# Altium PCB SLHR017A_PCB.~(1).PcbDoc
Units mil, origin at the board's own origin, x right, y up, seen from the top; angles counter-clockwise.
Board outline 3125 x 2100 mil, 2 copper layers (Top Layer, Bottom Layer), stack 61.2 mil thick; 71 components, 26 nets, 111 pads, 51 vias.
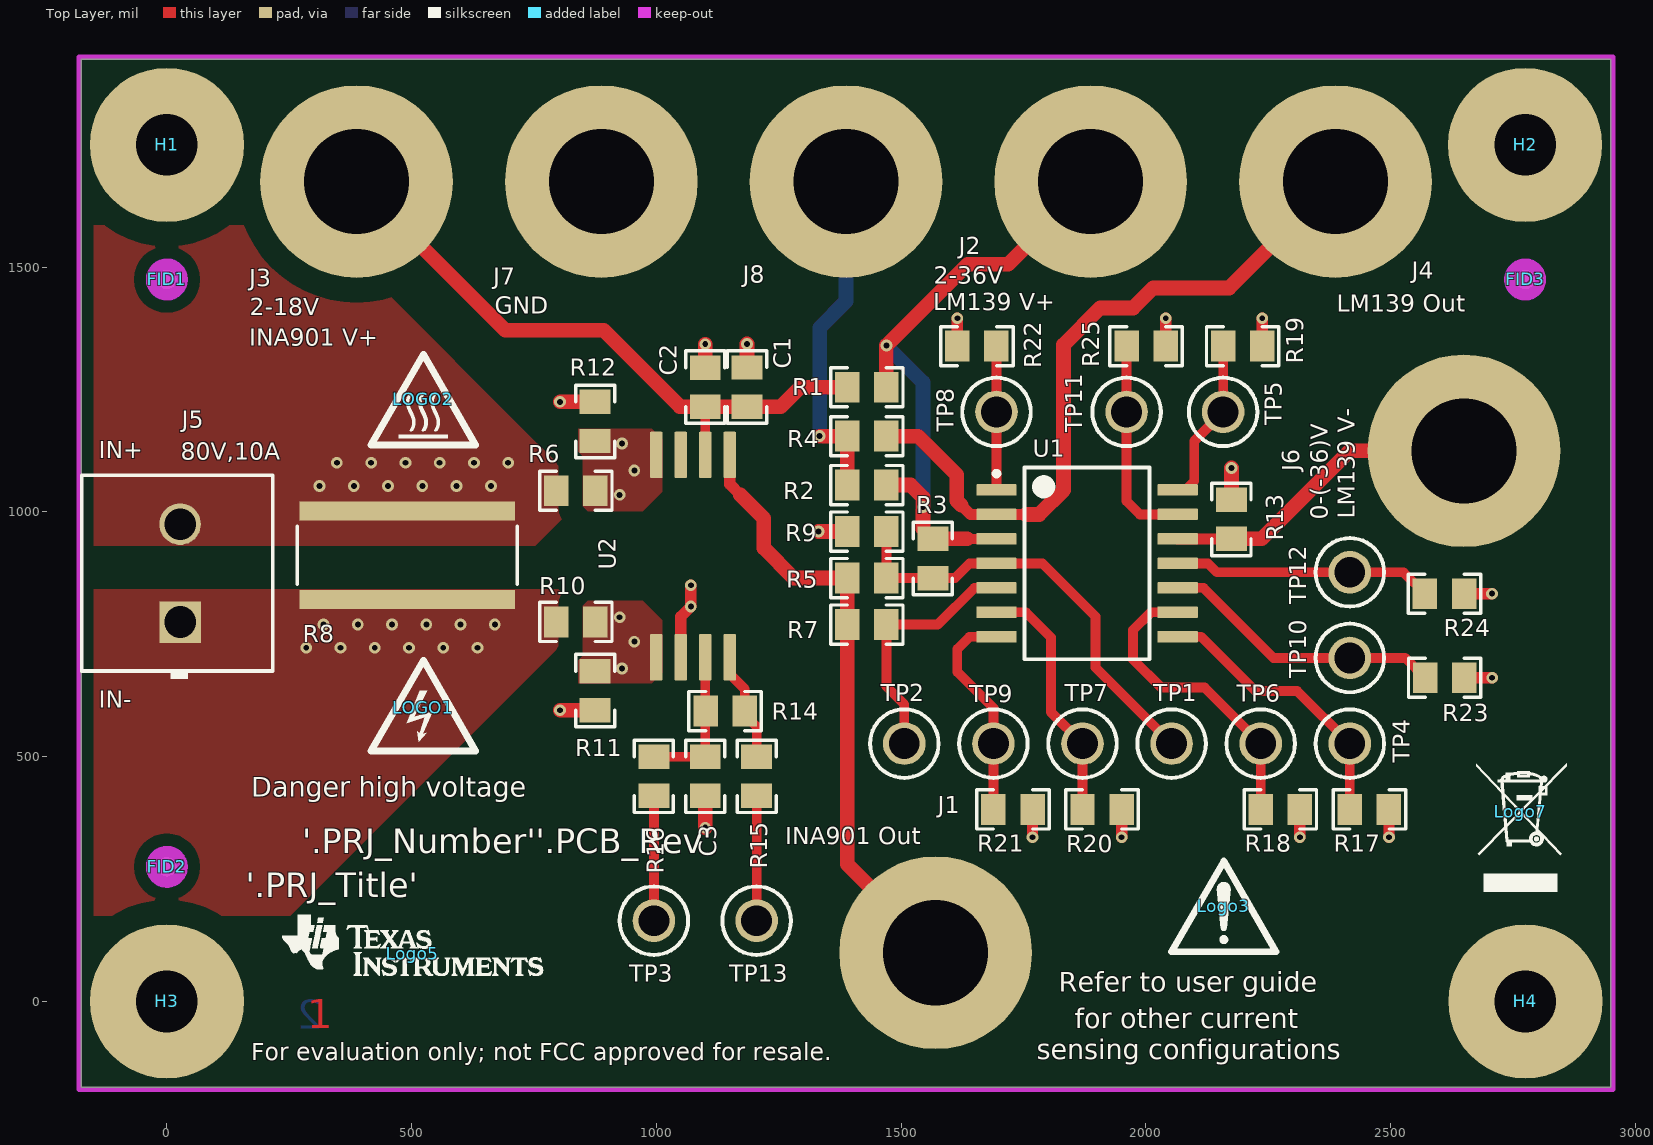
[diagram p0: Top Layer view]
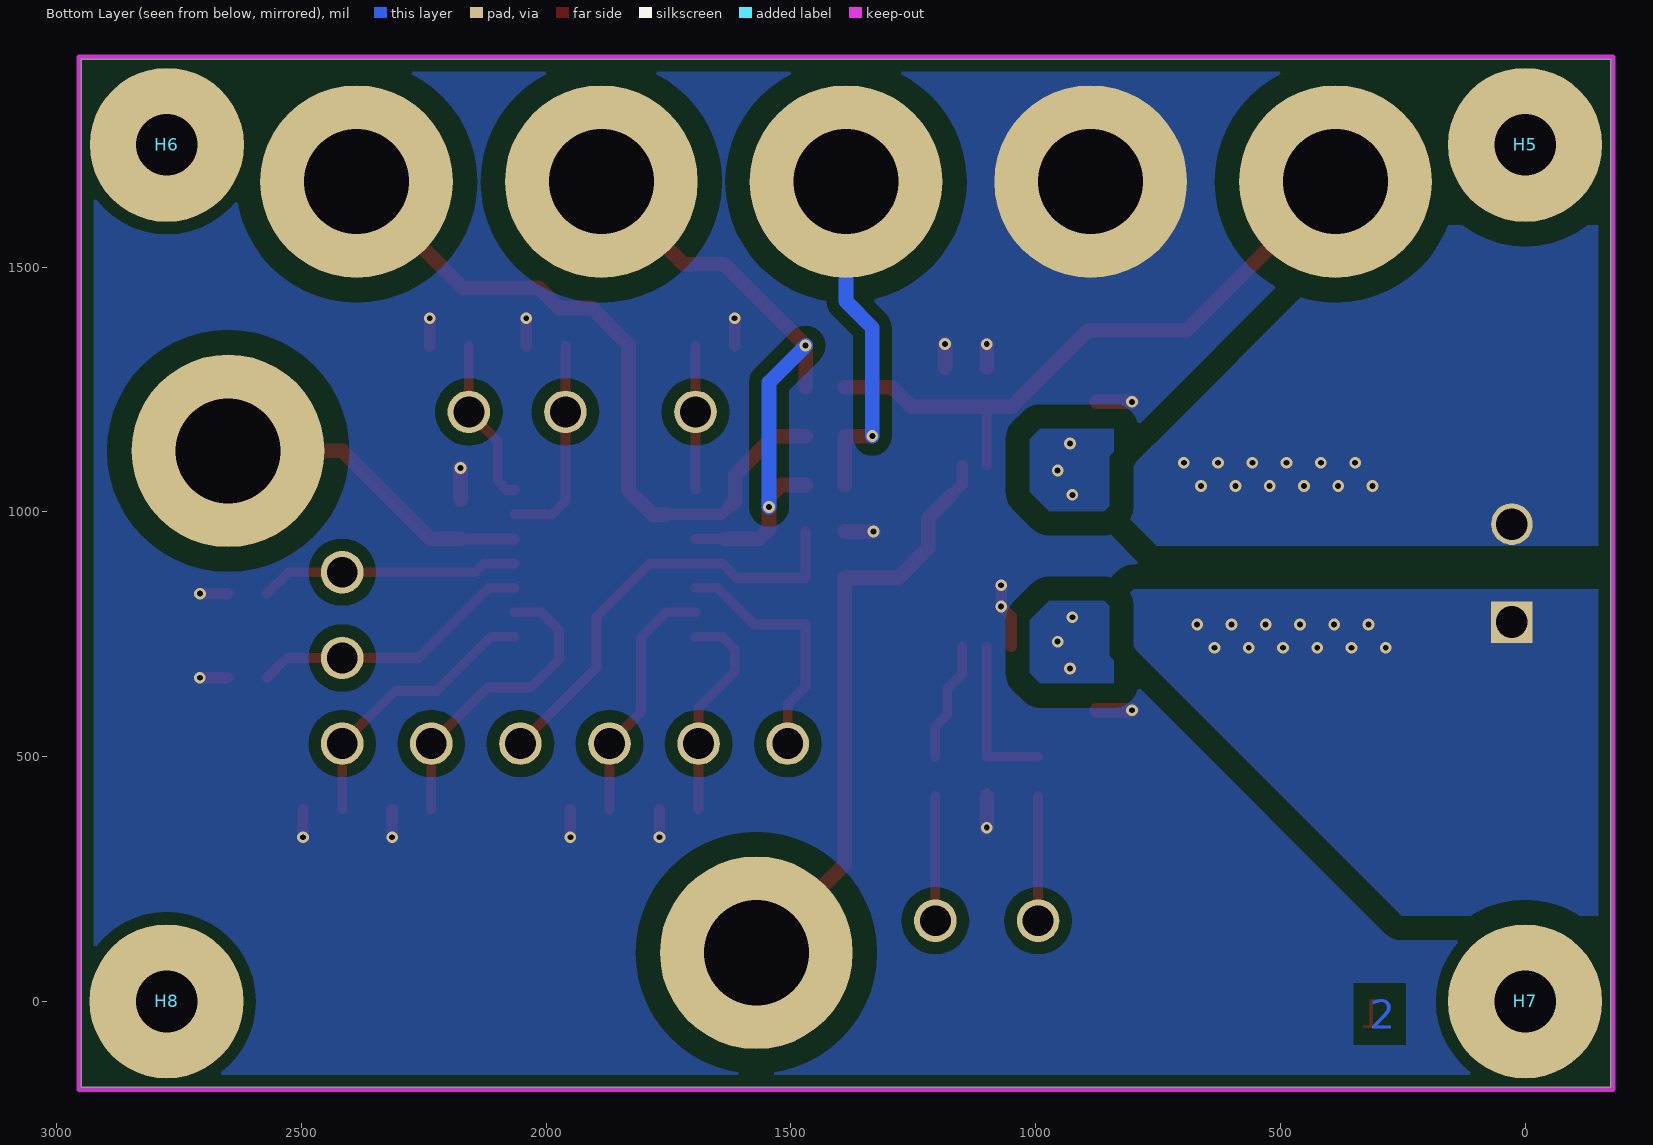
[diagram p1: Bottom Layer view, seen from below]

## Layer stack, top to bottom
Top Solder: solder mask 0.4, Solder Resist, Dk 3.5
Top Layer: signal copper 2.1
Dielectric1: core 57, FR-4 High Tg, Dk 4.8
Bottom Layer: signal copper 2.1
Bottom Solder: solder mask 0.4, Solder Resist, Dk 3.5

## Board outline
-175,-175 2950,-175 2950,1925 -175,1925
cut-out: -1791.23,-2214.56 -1781.23,-2214.56 -1781.23,-2204.56 -1791.23,-2204.56

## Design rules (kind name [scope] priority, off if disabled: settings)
AcuteAngle [All] p1: minimum=4.50000000000000E+0001 checktracksonly=FALSE
AssemblyTestPointUsage [All] p1: valid=2
Clearance Clearance_HV [InNetClass('HV_Net')] p1: gap=25 ignorepadtopadclearanceinfootprint=TRUE except(50: THPad-Poly Poly-Poly)
Clearance Clearance_Keepouts [((IsTrack Or IsArc) And Not InPoly) And IsFree and IsKeepOut vs ((IsTrack Or IsArc) And Not InPoly) And IsFree and IsKeepOut] p2: gap=0 ignorepadtopadclearanceinfootprint=FALSE
Clearance Clearance_Fiducial [InComponentClass('FiducialMark')] p3: gap=0 ignorepadtopadclearanceinfootprint=FALSE
Clearance Clearance_BoardEdge_MountingHoles [OnCopper and InComponentClass('Mounting Holes') vs IsKeepOut] p4: gap=40 ignorepadtopadclearanceinfootprint=FALSE except(15: Track-THPad)
Clearance Clearance_BoardEdge_Poly [OnCopper and InPoly vs IsKeepOut] p5: gap=25 ignorepadtopadclearanceinfootprint=FALSE
Clearance Clearance_Jack_Poly [InPolygon vs InPadClass('Jack')] p6: gap=25 ignorepadtopadclearanceinfootprint=FALSE except(50: Arc-Poly Track-Poly SMDPad-Poly THPad-Poly Via-Poly Fill-Poly Poly-Poly)
Clearance Clearance_Poly [InPolygon] p7: gap=25 ignorepadtopadclearanceinfootprint=FALSE
Clearance [All] p8: gap=15 ignorepadtopadclearanceinfootprint=FALSE
ComponentClearance ComponentClearance_MountingHoles_FiducialMarks [InComponentClass('Mounting Holes') vs InComponentClass('FiducialMark')] p1: gap=50 collisioncheckmode=3 verticalgap=10 showdistances=FALSE
ComponentClearance ComponentClearance_Logo [InComponentClass('Logo')] p2: gap=50 collisioncheckmode=3 verticalgap=100000 showdistances=FALSE
ComponentClearance ComponentClearance_ScrewToNut [(HasFootprint('NY PMS 440 0025 PH')) vs (HasFootprint('Keystone_1902C'))] p3: gap=0 collisioncheckmode=3 verticalgap=0 showdistances=FALSE
ComponentClearance ComponentClearance_MountingHoles [InComponentClass('Mounting Holes')] p4: gap=30 collisioncheckmode=3 verticalgap=100000 showdistances=FALSE
ComponentClearance [All] p5: gap=20 collisioncheckmode=3 verticalgap=10 showdistances=FALSE
DiffPairsRouting [All] p1: maxlimit=100 minlimit=10 mostfreqgap=10 toplayer_minwidth=15 toplayer_maxwidth=15 toplayer_prefwidth=15 bottomlayer_minwidth=15 bottomlayer_maxwidth=15 bottomlayer_prefwidth=15 maxuncoupledlength=1000
FabricationTestPointUsage TestPointUsage [All] p1: valid=2 allowmultiple=FALSE
FabricationTestpoint Testpoint [All] p1: side=3 testpointundercomponent=TRUE minsize=40 maxsize=100 preferedsize=60 minholesize=0 maxholesize=40 preferedholesize=32 testpointgrid=1 allowsidetop=TRUE allowsidebottom=TRUE usegrid=TRUE gridtolerance=0.01
FanoutControl Fanout_LCC [IsLCC] p1: bgadir=Out bgaviamode=Centered fanoutstyle=Auto fanoutdirection=Alternating viagrid=1 // Fanout_LCC (Default Rule)
FanoutControl Fanout_BGA [IsBGA] p2: bgadir=Out bgaviamode=Centered fanoutstyle=Auto fanoutdirection=Alternating viagrid=1 // Fanout_BGA (Default Rule)
FanoutControl Fanout_Default [All] p4: bgadir=Out bgaviamode=Centered fanoutstyle=Auto fanoutdirection=Alternating viagrid=1 // Fanout_Default (Default Rule)
FanoutControl Fanout_Small [(CompPinCount < 5)] p5: bgadir=Out bgaviamode=Centered fanoutstyle=Auto fanoutdirection=OutThenIn viagrid=1 // Fanout_Small (Default Rule)
HoleSize [All] p1: absolutevalues=TRUE maxlimit=251 minlimit=8 maxpercent=80.000 minpercent=20.000
MinimumAnnularRing [All] p1: minimumring=6
MinimumSolderMaskSliver MinimumSolderMaskSliver_Logo [InComponentClass('Logo') vs InComponentClass('Logo')] p1: minsoldermaskwidth=0.7
MinimumSolderMaskSliver [All] p2: minsoldermaskwidth=4
PlaneConnect [All] p1: planeconnectstyle=Relief reliefexpansion=10 reliefentries=4 reliefconductorwidth=10 reliefairgap=10
PolygonConnect [All] p1: connectstyle=Direct reliefconductorwidth=30 reliefentries=4 polygonreliefangle="90 Angle" airgapwidth=15
RoutingVias [All] p1: holewidth=12 width=24 viastyle="Through Hole" minholewidth=12 minwidth=24 maxholewidth=12 maxwidth=24
SilkToBoardRegionClearance [Not ((IsComment or IsDesignator) And (Hide <> 'False')) and not InRegion(1000,500,4000,800)] p1:
SilkToSilkClearance SilkToSilkClearance_Pb-FreeLogo [(HasFootprint('Pb-Free_Overlay_Medium') OR HasFootprint('Pb-Free_Overlay_Small')) vs (HasFootprint('Pb-Free_Overlay_Medium') OR HasFootprint('Pb-Free_Overlay_Small'))] p1: silktosilkclearance=0
SilkToSilkClearance [All] p2: silktosilkclearance=4
SilkToSolderMaskClearance SilkToComonentPadClearance [IsPad and InAnycomponent] p1: minsilkscreentomaskgap=5 clearancetoexposedcopper=TRUE
SilkToSolderMaskClearance "Silk to Solder Mask Opening" [All] p2: minsilkscreentomaskgap=4 clearancetoexposedcopper=FALSE
SolderMaskExpansion [All] p1: expansion=0
Width [All] p1: maxlimit=100 minlimit=6 preferedwidth=10 checkconnectedcopper=TRUE
15 further rules are at their usual default settings.

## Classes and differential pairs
net class HV_Net: NetJ5_1 NetJ5_2 NetR6_2 NetR10_2
pad class "HV Jack": J1-1
pad class Jack: J1-1 J2-1 J3-1 J4-1 J6-1 J7-1 J8-1
component class "Mounting Holes": H1 H2 H3 H4
component class Logo: Logo5
component class SLHR017A_Hardware: FID1 FID2 FID3 H1 H2 H3 H4 H5 H6 H7 H8 LOGO1 LOGO2 Logo3 Logo5 Logo6 Logo7 ZZ1 ZZ2 ZZ3
component class FiducialMark: FID1 FID2 FID3
component class AssemblyNote: ZZ1 ZZ2 ZZ3
component class SLHR017A_MainSheet: C1 C2 C3 J1 J2 J3 J4 J5 J6 J7 J8 R1 R2 R3 R4 R5 R6 R7 R8 R9 R10 R11 R12 R13 R14 R15 R16 R17 R18 R19 R20 R21 R22 R23 R24 R25 TP1 TP2 TP3 TP4 TP5 TP6 TP7 TP8 TP9 TP10 TP11 TP12 TP13 U1 U2 U4

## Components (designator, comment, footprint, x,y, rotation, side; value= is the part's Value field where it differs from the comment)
C1 "C0805C104K1RACTU" 0805_HV 1185.18,1255.18 r90 top locked value=0.1uF
C2 "C0805C103F1GACTU" 0805_HV 1100,1255 r90 top locked value=0.01uF
C3 "C0805C103F1GACTU" 0805_HV 1100,460 r270 top locked value=0.01uF
FID1 "Fiducial" Fiducial10-20 0,1475 r270 top locked
FID2 "Fiducial" Fiducial10-20 0,275 r0 top locked
FID3 "Fiducial" Fiducial10-20 2775,1475 r180 top locked
H1 "NY PMS 440 0025 PH" "NY PMS 440 0025 PH" 0,1750 r0 top locked
H2 "NY PMS 440 0025 PH" "NY PMS 440 0025 PH" 2775,1750 r0 top locked
H3 "NY PMS 440 0025 PH" "NY PMS 440 0025 PH" 0,0 r0 top locked
H4 "NY PMS 440 0025 PH" "NY PMS 440 0025 PH" 2775.53,0 r0 top locked
H5 "1902C" Keystone_1902C 0,1750 r180 bottom locked
H6 "1902C" Keystone_1902C 2775,1750 r180 bottom locked
H7 "1902C" Keystone_1902C 0,0 r180 bottom locked
H8 "1902C" Keystone_1902C 2775.53,0 r180 bottom locked
J1 "575-4" Keystone_575-4 1570.77,99.44 r0 top locked
J2 "575-4" Keystone_575-4 1887.5,1675 r0 top locked
J3 "575-4" Keystone_575-4 387.5,1675 r0 top locked
J4 "575-4" Keystone_575-4 2387.5,1675 r0 top locked
J5 "039544-3002" Molex_039544-3002 27.17,875 r90 top locked
J6 "575-4" Keystone_575-4 2650,1125 r0 top locked
J7 "575-4" Keystone_575-4 887.5,1675 r0 top locked
J8 "575-4" Keystone_575-4 1387.5,1675 r0 top locked
LOGO1 "DANGER HIGH VOLTAGE" IEC_HighVoltage_Small 524,599.72 r0 top
LOGO2 "CAUTION HOT SURFACE" IEC_HotSurface_Small 524,1229.94 r0 top
Logo3 "CAUTION.  READ USER GUIDE BEFORE USE" IEC_Caution_Small 2159.38,194.38 r0 top
Logo5 "Texas Instruments" TI_Stacked_Overlay_Small 502.13,97.86 r0 top
Logo6 "FCC disclaimer" FCC_disclaimer 1947.51,-1477.18 r270 top locked
Logo7 "WEEE logo" WEEE_Minimum 2765.79,387.53 r0 top
R1 "ERJ-6GEY0R00V" 0805_HV 1430,1255 r180 top locked value=0
R2 "ERJ-6GEY0R00V" 0805_HV 1430,1055 r180 top locked value=0
R3 "ERJ-6GEYJ153V" 0805_HV 1565,905 r90 top locked value=15k
R4 "ERJ-6GEYJ302V" 0805_HV 1430,1155 r180 top locked value=3.0k
R5 "ERJ-6GEY0R00V" 0805_HV 1430,865 r0 top locked value=0
R6 "ERJ-6GEY0R00V" 0805_HV 835.36,1043.51 r0 top locked value=0
R7 "ERJ-6GEY0R00V" 0805_HV 1430,770 r0 top locked value=0
R8 "KRL11050-C-R050-F-T1" 4320 490.99,911.59 r90 top locked value=0.05
R9 "ERJ-6GEYJ153V" 0805_HV 1430,960 r0 top locked value=15k
R10 "ERJ-6GEY0R00V" 0805_HV 835.36,775.33 r0 top locked value=0
R11 "ERJ-6GEY0R00V" 0805_HV 875,635 r90 top locked value=0
R12 "ERJ-6GEY0R00V" 0805_HV 875,1185 r270 top locked value=0
R13 "ERJ-6GEY0R00V" 0805_HV 2174.96,985 r270 top locked value=0
R14 "ERJ-6GEY0R00V" 0805_HV 1140.6,593.26 r180 top locked value=0
R15 "ERJ-6GEY0R00V" 0805_HV 1204.96,460 r90 top locked value=0
R16 "ERJ-6GEY0R00V" 0805_HV 994.96,460 r90 top locked value=0
R17 "ERJ-6GEY0R00V" 0805_HV 2456.86,392.33 r180 top value=0
R18 "ERJ-6GEY0R00V" 0805_HV 2274.81,392.33 r180 top value=0
R19 "ERJ-6GEY0R00V" 0805_HV 2198.08,1338.86 r180 top value=0
R20 "ERJ-6GEY0R00V" 0805_HV 1910.71,392.33 r180 top value=0
R21 "ERJ-6GEY0R00V" 0805_HV 1728.67,392.33 r180 top value=0
R22 "ERJ-6GEY0R00V" 0805_HV 1654.96,1338.86 r0 top value=0
R23 "ERJ-6GEY0R00V" 0805_HV 2610.76,661.33 r180 top value=0
R24 "ERJ-6GEY0R00V" 0805_HV 2610.39,833.07 r180 top value=0
R25 "ERJ-6GEY0R00V" 0805_HV 2000.77,1338.86 r180 top value=0
TP1 "5010" Keystone5010 2052.76,526.75 r90 top locked
TP2 "5010" Keystone5010 1506.62,526.75 r90 top locked
TP3 "5010" Keystone5010 994.96,164.96 r90 top locked
TP4 "5010" Keystone5010 2416.86,526.75 r90 top locked
TP5 "5010" Keystone5010 2158.08,1204.44 r90 top locked
TP6 "5010" Keystone5010 2234.81,526.75 r90 top locked
TP7 "5010" Keystone5010 1870.71,526.75 r90 top locked
TP8 "5010" Keystone5010 1694.96,1204.44 r90 top locked
TP9 "5010" Keystone5010 1688.67,526.75 r90 top locked
TP10 "5010" Keystone5010 2416.86,701.75 r90 top locked
TP11 "5010" Keystone5010 1960.77,1204.44 r90 top locked
TP12 "5010" Keystone5010 2416.86,876.75 r90 top locked
TP13 "5010" Keystone5010 1204.96,164.96 r90 top locked
U1 "LM139AWGRLQMLV" NAC0014A_N 1880,895 r0 top locked
U2 "INA901HKX/EM" HKX0008A_Custom_B 1075,910 r90 top locked
ZZ1 "These assemblies are ESD sensitive, ESD precautions shall be observed." AssemblyNote 4427.97,1278.79 r0 top
ZZ2 "These assemblies must be clean and free from flux and all contaminants. Use of no clean flux is not acceptable." AssemblyNote 4427.97,1190.24 r0 top
ZZ3 "These assemblies must comply with workmanship standards IPC-A-610 Class 2, unless otherwise specified." AssemblyNote 4427.97,1101.68 r0 top

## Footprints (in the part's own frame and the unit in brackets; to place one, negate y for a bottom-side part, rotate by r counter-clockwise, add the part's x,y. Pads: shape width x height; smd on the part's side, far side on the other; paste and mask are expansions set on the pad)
0805_HV [mil] "0805 with 30mil clearance between pads"
  rect 50x63 smd: 1(-40,0) 2(40,0)
  silkscreen extent -74,-40 74,40, body extent -43,-29 43,29, height 57
4320 [mm] "SUSUMU"
  rect 1x11.2 smd: 1(-2.3,0) 2(2.3,0)
  silkscreen extent -1.5,-5.7 1.5,5.7, body extent -2.6,-5.6 2.6,5.6, height 0.7
AssemblyNote [mil] "Assembly Note"
FCC_disclaimer [mil]
Fiducial10-20 [mm]
  round 1 smd mask+0.5: 1(0,0)
  Top Layer keep-out circle w1.178: c0,0 r0.5
HKX0008A_Custom_B [mm] "CFP, 8-Leads, Body 6.73x6.74mm (max), Pitch 1.27mm, IPC Medium Density"
  rrect15% 2.4x0.65 smd: 1(-5.25,1.905) 2(-5.25,0.635) 3(-5.25,-0.635) 4(-5.25,-1.905) 5(5.25,-1.905) 6(5.25,-0.635) 7(5.25,0.635) 8(5.25,1.905)
  body extent -3.25,-3.24 3.25,3.24, height 2.51
IEC_Caution_Small [mil]
  silkscreen extent -107,-93 107,92
IEC_HighVoltage_Small [mil]
  silkscreen extent -107,-88 107,97
IEC_HotSurface_Small [mil]
  silkscreen extent -107,-93 107,92
Keystone5010 [mil] "Keystone Multipurpose loops"
  round 87 hole 63: 1(0,0)
  silkscreen extent -70,-70 70,70, body extent -63,-63 63,62, height 319
Keystone_575-4 [mm] "Banana Jack"
  round 10 hole 5.45: 1(0,0)
  body extent -3.95,-3.95 3.92,3.93, height 2.36
Keystone_1902C [mil] "Hex Standoff, 4-40 threaded, nylon"
  round 1 on Mech4: 0(0,0)
  body extent -145,-126 146,126, height 501
Molex_039544-3002 [mm] "Terminal Block, 5.08mm, 2x1, TH"
  rect 2.15x2.15 hole 1.65: 1(-2.54,0)
  round 2.15 hole 1.65: 2(2.54,0)
  silkscreen extent -5.5,-4.8 5.08,5.11, body extent -5.08,-4.8 5.08,5.11, height 14.48
NAC0014A_N [mm] "CFP-14"
  rrect17% 2.1x0.6 smd: 1(-4.7,3.81) 2(-4.7,2.54) 3(-4.7,1.27) 4(-4.7,0) 5(-4.7,-1.27) 6(-4.7,-2.54) 7(-4.7,-3.81) 8(4.7,-3.81) 9(4.7,-2.54) 10(4.7,-1.27) 11(4.7,0) 12(4.7,1.27) 13(4.7,2.54) 14(4.7,3.81)
  silkscreen extent -4.82,-4.97 3.25,4.97, body extent -5.21,-4.95 5.21,4.95, height 1.99
"NY PMS 440 0025 PH" [mm] "4-40 nylon screw and mounting hole"
  round 8 hole 3.2: 1(0,0)
  body extent -3.3,-3.3 3.3,3.3, height 2.69
TI_Stacked_Overlay_Small [mil]
  silkscreen extent -267,-46 267,80
WEEE_Minimum [mil] "WEEElie bin"
  silkscreen extent -91,-164 94,99

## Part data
C1: library part CMP-0007722-2, "CAP, CERM, 0.1 uF, 100 V, +/- 10%, X7R, 0805", Cap_Case=0805, Manufacturer=Kemet, Supplier Part Number 1=399-3486-1-ND, TempCo=X7R, Tolerance_%=10%, Value1="0.064 ohm", Value2=100V, ValueDisplayed=0.1uF
C2 C3: library part CMP-0007716-2, "CAP, CERM, 0.01 uF, 100 V, +/- 1%, C0G/NP0, 0805", Cap_Case=0805, Manufacturer=Kemet, Supplier Part Number 1=399-11160-1-ND, TempCo=C0G/NP0, Tolerance_%=1%, Value1=Unknown, Value2=100V, ValueDisplayed=0.01uF
FID1 FID2 FID3: library part CMP-0077181-1, "Fiducial mark.  There is nothing to buy or mount.", Manufacturer=N/A
H1 H2 H3 H4: library part CMP-0003617-1, "Machine Screw, Round, #4-40 x 1/4, Nylon, Philips panhead", Manufacturer="B&F Fastener Supply", Supplier Part Number 1=H542-ND
H5 H6 H7 H8: library part CMP-0003610-1, "Standoff, Hex, 0.5\"L #4-40 Nylon", Manufacturer=Keystone, Supplier Part Number 1=36-1902C-ND
J1 J2 J3 J4 J6 J7 J8: library part CMP-0055165-2, "Standard Banana Jack, Uninsulated, 5.5mm", Manufacturer=Keystone, Supplier Part Number 1=36-575-4-ND
J5: library part CMP-0055345-1, "Terminal Block, 5.08mm, 2x1, TH", Color=Black, Current_A=15A, Manufacturer=Molex, Supplier Part Number 1=WM7853-ND, Voltage_V=300V
LOGO1: library part CMP-0074835-1, "IEC 61010-1 High Voltage Warning"
LOGO2: library part CMP-0074837-1, "IEC 61010-1 Hot Surface Warning"
Logo3: library part CMP-0074836-1, "IEC 61010-1 Caution Warning"
Logo5: library part CMP-0074838-1, "Texas Instrument Corporate Signature"
Logo6: library part CMP-0074847-1, "FCC_disclaimer"
Logo7: library part CMP-0074769-1
R1 R2 R5 R6 R7 R10 R11 R12 R13 R14 R15 R16 R17 R18 R19 R20 R21 R22 R23 R24 R25: library part CMP-0020616-3, "RES, 0, 5%, 0.125 W, AEC-Q200 Grade 0, 0805", Manufacturer=Panasonic, Power_W=125mW, Supplier Part Number 1=P0.0ACT-ND, TempCo="600 ppm/C", Tolerance_%=5%, Value2=0.125W, Value_Code=0000, ValueDisplayed=0
R3 R9: library part CMP-0020646-3, "RES, 15 k, 5%, 0.125 W, AEC-Q200 Grade 0, 0805", Manufacturer=Panasonic, Power_W=125mW, Supplier Part Number 1=P15KACT-ND, TempCo="200 ppm/C", Tolerance_%=5%, Value2=0.125W, Value_Code=15k0, ValueDisplayed=15k
R4: library part CMP-0020698-3, "RES, 3.0 k, 5%, 0.125 W, AEC-Q200 Grade 0, 0805", Manufacturer=Panasonic, Power_W=125mW, Supplier Part Number 1=P3.0KACT-ND, TempCo="200 ppm/C", Tolerance_%=5%, Value2=0.125W, Value_Code=3k00, ValueDisplayed=3.0k
R8: library part CMP-0015099-2, "RES, 0.05, 1%, 6 W, 4320_WIDE", Manufacturer="Susumu Co Ltd", Power_W=6W, Supplier Part Number 1=KRL11C.050CT-ND, TempCo="50 ppm/C", Tolerance_%=1%, Value_Code=R050, ValueDisplayed=0.05
TP1 TP2 TP3 TP4 TP5 TP6 TP7 TP8 TP9 TP10 TP11 TP12 TP13: library part CMP-0055147-1, "Test Point, Multipurpose, Red, TH", Color=Red, Manufacturer=Keystone, Supplier Part Number 1=36-5010-ND
U1: library part CMP-0068426-2, "Low Power Low Offset Voltage Quad Comparator, NAC0014A (CFP-14)", Manufacturer="Texas Instruments", Operating Temperature Range="-55 to 125 C", Rating=Space
U2: library part CMP-0081563-2, "Voltage Output, Unidirectional Measurement Current-Shunt Monitor, HKX0008A (CFP-8)", Alternate Manufacturer="Texas Instruments", Rating=Space
ZZ1: library part CMP-0077236-1
ZZ2: library part CMP-0077237-1
ZZ3: library part CMP-0077238-1

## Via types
v1: diameter 24, hole 12, Top Layer to Bottom Layer, tented both sides, 51 vias

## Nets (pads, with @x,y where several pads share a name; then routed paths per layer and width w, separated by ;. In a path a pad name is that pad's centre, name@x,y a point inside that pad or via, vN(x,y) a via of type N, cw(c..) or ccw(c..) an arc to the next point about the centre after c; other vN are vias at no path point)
GND: C1.2 C2.2 C3.2 J7.1 R9.1 R11.1 R12.1 R13.1 R17.1 R18.1 R19.1 R20.1 R21.1 R22.1 R23.1 R24.1 R25.1 U2.2 | length 1074.6
  Top Layer w23: U2.2@1050,724.96 1050,786.23 v1(1070.49,806.72) v1(1070.49,850.26) ; R22.1 v1(1614.96,1395.85) ; v1(1768.67,335.33) R21.1 ; v1(1950.71,335.33) R20.1 ; R25.1 v1(2040.77,1395.85) ; R19.1 v1(2238.08,1395.85) ; v1(2314.81,335.33) R18.1 ; v1(2496.86,335.33) R17.1 ; R24.1 v1(2707.39,833.07) ; R23.1 v1(2707.75,661.33)
  Top Layer w30: v1(803.35,595) R11.1 ; v1(803.35,1225) R12.1 ; v1(1100,355) C3.2 ; C2.2 v1(1100,1342.91) ; C1.2 v1(1185.18,1343.09) ; v1(1331.23,960) R9.1 ; R13.1 v1(2174.96,1090)
NetC1_1: C1.1 C2.1 J3.1 R1.2 U2.6 | length 1329.6
  Top Layer w20: U2.6@1100,1095.04 U2.6 C2.1
  Top Layer w30: J3.1 691.32,1371.18 892.31,1371.18 1048.49,1215 C2.1 1185,1215 C1.1 1254.02,1215.18 1293.85,1255 R1.2
NetC3_1: C3.1 R14.2 R16.2 U2.3 | length 330
  Top Layer w20: R16.2 C3.1 U2.3 U2.3@1100,724.96
NetJ1_1: J1.1 R5.1 R7.1 U2.5 | length 1233.7
  Top Layer w23: U2.5@1150,1095.04 1150,1056.77 1172.12,1034.65
  Top Layer w30: 1172.12,1034.65 1219.65,987.12 1219.65,926.49 1281.14,865 R5.1 R7.1 1390,280.21 J1.1
NetJ2_1: J2.1 R1.1 R2.1 R3.2 U1.3 | length 1310.8
  Top Layer w20: 1635,945 U1.3
  Top Layer w30: R2.1 1520,1055 1544.77,1030.23 v1(1544.77,1010) 1544.77,965.23 R3.2 1635,945 ; R1.1 v1(1470,1340) 1636.27,1506.27 1718.77,1506.27 J2.1
  Bottom Layer w30: v1(1470,1340) 1544.77,1265.23 v1(1544.77,1010)
NetJ4_1: J4.1 R4.1 U1.2 | length 1470.8
  Top Layer w23: 1623.24,1013.54 1641.78,995 U1.2 1755.43,995
  Top Layer w30: R4.1 1535.27,1155 1614.02,1076.26 1614.02,1022.76 1623.24,1013.54 ; 1755.43,995 1782.21,995 1831.95,1044.73 1831.95,1341.77 1907.08,1416.9 1974.2,1416.9 2015.07,1457.77 2170.27,1457.77 J4.1
NetJ5_1: J5.1 R8.1 R10.1
  other v1: 284.71,722.65 354.71,722.65 424.71,722.65 494.71,722.65 564.71,722.65 634.71,722.65 320.06,770.19 390.06,770.19 460.06,770.19 530.06,770.19 600.06,770.19 670.06,770.19
NetJ5_2: J5.2 R6.1 R8.2
  other v1: 311.93,1052.99 381.93,1052.99 451.93,1052.99 521.93,1052.99 591.93,1052.99 661.93,1052.99 347.28,1100.53 417.28,1100.53 487.28,1100.53 557.28,1100.53 627.28,1100.53 697.28,1100.53
NetJ6_1: J6.1 R13.2 U1.12 | length 659.5
  Top Layer w23: U1.12 R13.2
  Top Layer w30: R13.2 2237.09,945 2417.09,1125 J6.1
NetJ8_1: J8.1 R2.2 R4.2 | length 698.7
  Top Layer w30: v1(1333.63,1155) R4.2 R2.2
  Bottom Layer w30: v1(1333.63,1155) 1333.63,1376.62 1387.5,1430.48 J8.1
NetR3_1: R3.1 R5.2 R9.2 TP1.1 U1.4 | length 903.8
  Top Layer w20: R9.2 R5.2 R3.1 1610,865 1640,895 U1.4 1788.74,895 1897.5,786.24 1897.5,682.01 TP1.1
NetR6_2: R6.2 R12.2 U2.8
  other v1: 925,1035 955,1085 930,1140
NetR7_2: R7.2 TP2.1 U1.5 | length 514.4
  Top Layer w20: TP2.1 1506.62,606.6 1470,643.21 R7.2 1575,770 1650,845 U1.5
NetR10_2: R10.2 R11.2 U2.1
  other v1: 930,680 955,735 925,785
NetR14_1: R14.1 R15.2 U2.4 | length 247.7
  Top Layer w20: U2.4@1150,724.96 U2.4 1150,668.95 1180.6,638.34 R14.1 1180.6,586.22 1204.96,561.86 R15.2
NetR15_1: R15.1 TP13.1 | length 240
  Top Layer w20: TP13.1@1204.96,179.96 R15.1
NetR16_1: R16.1 TP3.1 | length 240
  Top Layer w20: TP3.1@994.96,179.96 R16.1
NetR17_2: R17.2 TP4.1 U1.8 | length 576.6
  Top Layer w20: U1.8 2113.48,745 2224.26,634.22 2309.38,634.22 TP4.1 R17.2
NetR18_2: R18.2 TP6.1 U1.9 | length 632.4
  Top Layer w20: U1.9 2010.17,795 1974.08,758.91 1974.08,698.8 2031.61,641.27 2120.29,641.27 TP6.1 R18.2
NetR19_2: R19.2 TP5.1 U1.14 | length 341.8
  Top Layer w20: U1.14 2081.13,1045 2099.14,1063.02 2099.14,1145.5 TP5.1 R19.2
NetR20_2: R20.2 TP7.1 U1.6 | length 510.6
  Top Layer w20: U1.6 1755,795 1806.61,743.39 1806.61,590.85 TP7.1 R20.2
NetR21_2: R21.2 TP9.1 U1.7 | length 448.5
  Top Layer w20: R21.2 TP9.1 1688.67,599.23 1615,672.9 1615,720 1640,745 U1.7
NetR22_2: R22.2 TP8.1 U1.1 | length 293.9
  Top Layer w20: U1.1 TP8.1 R22.2
NetR23_2: R23.2 TP10.1 U1.10 | length 581.8
  Top Layer w20: U1.10 2117.88,845 2261.13,701.75 TP10.1 2530.33,701.75 R23.2
NetR24_2: R24.2 TP12.1 U1.11 | length 531
  Top Layer w20: U1.11 2127.37,895 2145.62,876.75 TP12.1 2526.71,876.75 R24.2
NetR25_2: R25.2 TP11.1 U1.13 | length 432.2
  Top Layer w20: R25.2 TP11.1 1960.77,1022.12 1987.89,995 U1.13
pads on no net: FID1.1 FID2.1 FID3.1 H1.1 H2.1 H3.1 H4.1 H5.0 H6.0 H7.0 H8.0 U2.7

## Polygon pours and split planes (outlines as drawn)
NetJ5_2 on Top Layer "GND" (solid, remove dead copper, pour order 267): -175.09,930.77 752.62,930.77 820.22,998.37 820.22,1076.25 717.82,1178.65 310.93,1585.54 -173.01,1585.54
NetJ5_1 on Top Layer "GND" (solid, remove dead copper, pour order 266): -174.94,842.31 799.54,842.31 820.22,821.63 820.22,743.75 717.82,641.35 251.68,175.21 -172.82,175.21
NetR6_2 on Top Layer "GND" (solid, remove dead copper, pour order 265): 840.29,1170.15 840.29,1122.86 849.75,1113.4 849.75,1011.89 859.85,1001.78 972.21,1001.78 1011.88,1041.45 1011.88,1148.44 990.17,1170.15
NetR10_2 on Top Layer "GND" (solid, remove dead copper, pour order 264): 840.29,649.85 840.29,696.87 849.75,706.32 849.75,808.11 859.85,818.22 972.21,818.22 1011.88,778.55 1011.88,671.56 990.17,649.85
NetJ5_2 on Bottom Layer "GND" (solid, remove dead copper, pour order 271): -175.09,930.77 752.62,930.77 820.22,998.37 820.22,1076.25 717.82,1178.65 310.93,1585.54 -173.01,1585.54
NetJ5_1 on Bottom Layer "GND" (solid, remove dead copper, pour order 270): -174.94,842.31 799.54,842.31 820.22,821.63 820.22,743.75 717.82,641.35 251.68,175.21 -172.82,175.21
NetR10_2 on Bottom Layer "GND" (solid, remove dead copper, pour order 268): 840.29,649.85 840.29,696.87 849.75,706.32 849.75,808.11 859.85,818.22 972.21,818.22 1011.88,778.55 1011.88,671.56 990.17,649.85
NetR6_2 on Bottom Layer "GND" (solid, remove dead copper, pour order 269): 840.29,1170.15 840.29,1122.86 849.75,1113.4 849.75,1011.89 859.85,1001.78 972.21,1001.78 1011.88,1041.45 1011.88,1148.44 990.17,1170.15
GND on Bottom Layer "GND" (solid, remove dead copper, pour order 272): -174.92,-174.96 2949.91,-174.96 2949.92,-174.96 2949.92,1925.05 2949.89,1925.07 -174.89,1925.07 -175,1924.96

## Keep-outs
Keep-Out Layer:
  lines w10: -180,-180 -180,1930 2955,1930 2955,-180 -180,-180
  text ".Layer_Name" at -522.23,-1539.06 h60

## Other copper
Top Layer:
  text "1" at 287.08,-55.09 h60
  text ".Layer_Name" at -522.23,-1539.06 h60
Bottom Layer:
  text "2" at 316.97,-55.48 h60
  text ".Layer_Name" at -522.23,-1539.06 h60

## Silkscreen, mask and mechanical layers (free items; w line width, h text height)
Top Overlay:
  text "2-36V" at 1566.56,1466.79 h35
  text "LM139 V+" at 1566.01,1412.12 h35
  text "LM139 Out" at 2390.02,1409.42 h35
  text "GND" at 669.35,1405.39 h35
  text "2-18V" at 169.23,1402.02 h35
  text "INA901 V+" at 168.19,1339.58 h35
  text "IN+" at -139.72,1109.97 h35
  text "80V,10A" at 28.26,1106.78 h35
  text "LM139 V-" at 2427.31,986.4 h35 r90
  text "0-(-36)V" at 2371.89,984.24 h35 r90
  text "IN-" at -139.72,599.99 h35
  text "Danger high voltage" at 172.24,418.2 h40
  text "INA901 Out" at 1263.83,321.35 h35
  text "'.PRJ_Number''.PCB_Rev'" at 276.6,302.79 h50
  text "'.PRJ_Title'" at 161.3,212.89 h50
  text "Refer to user guide" at 1822.52,19.52 h40
  text "for other current" at 1854.54,-54.96 h40
  text "sensing configurations" at 1776.8,-118.4 h40
  text ".Layer_Name" at -522.23,-1539.06 h60
Bottom Overlay:
  text ".Layer_Name" at -522.23,-1539.06 h60
Top Paste:
  text ".Layer_Name" at -522.23,-1539.06 h60
Bottom Paste:
  text ".Layer_Name" at -522.23,-1539.06 h60
Top Solder:
  text ".Layer_Name" at -522.23,-1539.06 h60
  text ".Layer_Name" at -522.23,-1539.06 h60
Bottom Solder:
  text ".Layer_Name" at -522.23,-1539.06 h60
Drill Guide:
  text ".Layer_Name" at -522.23,-1539.06 h60
M1 Board Outline:
  the board outline again, w10
  text ".Layer_Name" at -522.23,-1539.06 h60
M2 Board Dimensions:
  rectangle: -1099.23,-955.56 -974.23,-830.56
  rectangle: -974.23,-1080.56 -599.23,-955.56
  lines w7: -1099.23,-955.56 -99.23,-955.56 ; -974.23,-1080.56 -974.23,-830.56 ; -849.23,-1080.56 -849.23,-830.56 ; -599.23,-1080.56 -599.23,-830.56 ; -349.23,-1080.56 -349.23,-830.56 ; -1099.23,-1080.56 -99.23,-1080.56 -99.23,-830.56 -1099.23,-830.56 -1099.23,-1080.56
  text ".Layer_Name" at -522.23,-1539.06 h60
M3 3D STEP Top:
  text ".Layer_Name" at -522.23,-1539.06 h60
M4 3D STEP Bottom:
  text ".Layer_Name" at -522.23,-1539.06 h60
M5 Assembly Top:
  lines w10: -1391.23,-1610.73 5208.77,-1610.73 ; -1391.23,-1407.4 5210.77,-1407.4 ; -1391.23,-1204.06 -1391.23,-1814.06 2613.77,-1814.06 5210.77,-1814.06 5210.77,-1204.06 -1390.73,-1204.06 -1390.73,-1814.06 184.77,-1814.06 ; 1073.77,-1814.06 1073.77,-1204.06 ; 2340.77,-1407.4 2340.77,-1204.06 ; 3180.77,-1407.4 3180.77,-1204.06 ; 3802.77,-1820.56 3802.77,-1617.73
  text "COMPONENTS MARKED 'DNP' SHOULD NOT BE POPULATED." at 54.27,-999.06 h60
  text "ASSEMBLY VARIANT:" at 53.77,-1114.56 h60
  text ".VariantName" at 1089.77,-1114.56 h60
  text "PCB VIEWED FROM TOP SIDE" at -1327.73,-1336.23 h60
  text "BOARD #:" at 1148.77,-1336.23 h60
  text ".PRJ_Number" at 1694.27,-1336.23 h60
  text "REV:" at 2538.77,-1336.23 h60
  text ".PCB_Rev" at 2830.27,-1336.23 h60
  text "SVN REV:" at 3376.77,-1336.23 h60
  text ".VersionControl_RevNumber" at 3882.77,-1336.23 h60
  text "TID #:" at 1148.77,-1539.56 h60
  text ".TID" at 1694.27,-1539.56 h60
  text "PLOT NAME =" at -1327.73,-1744.9 h60
  text ".plot_File_Name" at -522.23,-1744.9 h60
  text "GENERATED    :" at 1150.77,-1744.9 h60
  text ".Print_Date" at 2020.27,-1744.9 h60
  text ".Print_Time" at 2749.27,-1744.9 h60
  text "TEXAS INSTRUMENTS" at 4013.77,-1744.9 h60
M6 Assembly Bottom:
  lines w10: -1391.73,-1407.9 5210.27,-1407.9 ; -1389.73,-1611.23 5210.27,-1611.23 ; 16.27,-1821.06 16.27,-1618.23 ; 638.27,-1407.9 638.27,-1204.56 ; 1478.27,-1407.9 1478.27,-1204.56 ; 2745.27,-1814.56 2745.27,-1204.56 ; 3634.27,-1814.56 5209.77,-1814.56 5209.77,-1204.56 -1391.73,-1204.56 -1391.73,-1814.56 1205.27,-1814.56 5210.27,-1814.56 5210.27,-1204.56
  text "COMPONENTS MARKED 'DNP' SHOULD NOT BE POPULATED." at 5002.77,-998.56 h60
  text ".VariantName" at 3958.77,-1114.56 h60
  text "ASSEMBLY VARIANT:" at 4997.77,-1114.56 h60
  text ".VersionControl_RevNumber" at -63.73,-1336.73 h60
  text "SVN REV:" at 442.27,-1336.73 h60
  text ".PCB_Rev" at 988.77,-1336.73 h60
  text "REV:" at 1280.27,-1336.73 h60
  text ".PRJ_Number" at 2124.77,-1336.73 h60
  text "BOARD #:" at 2670.27,-1336.73 h60
  text "PCB VIEWED FROM BOTTOM SIDE" at 5146.77,-1336.73 h60
  text ".TID" at 2124.77,-1540.06 h60
  text "TID #:" at 2670.27,-1540.06 h60
  text "TEXAS INSTRUMENTS" at -194.73,-1745.4 h60
  text ".Print_Time" at 1069.77,-1745.4 h60
  text ".Print_Date" at 1798.77,-1745.4 h60
  text "GENERATED    :" at 2668.27,-1745.4 h60
  text ".plot_File_Name" at 4341.27,-1745.4 h60
  text "PLOT NAME =" at 5146.77,-1745.4 h60
M7 LPKF Text Top:
  text ".Layer_Name" at -522.23,-1539.06 h60
M8 LPKF Text Bottom:
  text ".Layer_Name" at -522.23,-1539.06 h60
M9 Title Sheet:
  drawing of 57 lines, arcs and shapes, not listed
  text "1" at -359.39,7355.94 h70
  text "2" at 2136.27,7355.94 h70
  text "3" at 4625.61,7355.94 h70
  text "4" at 7132.28,7355.94 h70
  text "5" at 9631.27,7355.94 h70
  text "6" at 12136.27,7355.94 h70
  text "A" at -1515.73,6212.94 h70
  text "A" at 13284.27,6212.94 h70
  text "B" at -1515.73,3832.94 h70
  text "B" at 13284.27,3832.94 h70
  text "C" at -1515.73,1457.94 h70
  text "C" at 13284.27,1457.94 h70
  text "PROJECT TITLE:" at 10244.27,-403.06 h45
  text ".PRJ_Title" at 10294.27,-536.39 h70
  text "DESIGNED FOR:" at 10244.27,-704.06 h45
  text ".PRJ_Customer" at 10294.27,-844.06 h70
  text "D" at -1515.73,-912.06 h70
  text "D" at 13284.27,-912.06 h70
  text "FILE NAME:" at 10244.27,-1004.06 h45
  text ".PCB_File_Name_No_Path" at 10294.27,-1124.06 h70
  text "Texas Instruments (TI) and/or its licensors do not warrant the accuracy or completeness of this specification" at 5274.77,-1285.9 h45
  text "ENGINEER:" at 10244.27,-1294.06 h45
  text "LAYOUT BY:" at 11749.27,-1294.06 h45
  text "or any information contained therein. TI and/or its licensors do not warrant that this design will meet" at 5229.79,-1398.57 h45
  text ".PRJ_Engineer" at 10294.27,-1449.05 h70
  text ".PCB_Layout" at 11799.77,-1449.05 h70
  text "the specifications, will be suitable for your application or fit for any particular purpose, or will operate in" at 5229.79,-1511.23 h45
  text ".Layer_Name" at -522.23,-1539.06 h60
  text "ALTIUM DESIGNER VERSION:" at 11749.27,-1604.06 h45
  text "an implementation. TI and/or its licensors do not warrant that the design is production worthy. You should" at 5229.79,-1623.9 h45
  text "completely validate and test your design implementation to confirm the system functionality for your application." at 5274.77,-1736.56 h45
  text ".print_Scale" at 10294.27,-1737.39 h70
  text ".Application_BuildNumber" at 11799.77,-1737.39 h70
  text "1" at -359.39,-1944.06 h70
  text "2" at 2136.27,-1944.06 h70
  text "3" at 4625.61,-1944.06 h70
  text "4" at 7132.28,-1944.06 h70
  text "5" at 9631.27,-1944.06 h70
  text "6" at 11488.98,-1949.87 h70
  text "WO#307451-7449-D" at 11888.89,-1952.37 h70
M10 Fab Notes:
  drawing of 189 lines, arcs and shapes, not listed
  text "DESIGN INFORMATION" at 11296.29,5675.61 h60
  text "20" at 11706.72,5544.28 h60
  text "MIN. TRACK WIDTH:" at 10651.73,5543.49 h60
  text "MIL" at 11902.73,5543.49 h60
  text "MIN. CLEARANCE:" at 10651.73,5419.36 h60
  text "MIL" at 11902.73,5419.36 h60
  text "19.7" at 11661.15,5416.95 h60
  text "24" at 11687.7,5303.69 h60
  text "MIN. VIA PAD SIZE:" at 10651.73,5295.23 h60
  text "MIL" at 11902.73,5295.23 h60
  text "0.05mm (2MIL)" at 11346.73,5165.33 h60
  text "MINIMUM ANNULAR RING" at 10322.5,5157.11 h60
  text "EXTERNAL" at 12054.73,5157.11 h60
  text "PER" at 10522.5,5046.99 h60
  text "IPC-D-275 CLASS 2 LEVEL C" at 10742.5,5046.98 h60
  text "MIL, HOLES" at 12230.73,4946.51 h60
  text "+/-" at 11838.27,4937.92 h60
  text "+/-" at 12692.27,4937.92 h60
  text "REGISTRATION TOLERANCES:" at 10322.5,4936.86 h60
  text "METAL" at 11522.27,4936.86 h60
  text "5" at 12098.47,4936.86 h60
  text "3" at 12931.47,4936.86 h60
  text "MIL" at 13047.73,4936.86 h60
  text "HOLE SIZE TOLERANCE (UNLESS OTHERWISE SPECIFIED):" at 10322.5,4838.54 h60
  text "+/-" at 12692.27,4835.67 h60
  text "3" at 12931.47,4834.61 h60
  text "MIL" at 13047.73,4834.6 h60
  text "MATERIAL:" at 10247.73,4696.96 h60
  text "FR-4 High Tg" at 11234.17,4568.43 h60
  text "FR-408" at 10668.73,4555.93 h60
  text "OTHER" at 12156.73,4555.93 h60
  text "X" at 11085.86,4554.44 h60
  text "62 MIL (1.6mm) +/-10%" at 10988.83,4412.9 h60
  text "X" at 10868.74,4410.44 h60
  text "THICKNESS:" at 10322.5,4404.68 h60
  text "OTHER" at 12273.73,4404.68 h60
  text "TOLERANCE:" at 10322.5,4266.36 h60
  text "X" at 11170.74,4266.36 h60
  text "ANSI IPC-6012 TYPE 3 CLASS 2" at 11348.75,4266.36 h60
  text "OTHER +/-" at 11348.73,4122.17 h60
  text "BOW & TWIST:" at 10322.5,3976.98 h60
  text "X" at 11170.74,3976.98 h60
  text "ANSI IPC-6012 TYPE 3 CLASS 2" at 11348.75,3976.98 h60
  text "OTHER +/-" at 11348.73,3830.29 h60
  text "DRILLING:" at 10247.73,3699.67 h60
  text "NC_DRILL FILES" at 12008.73,3594.48 h60
  text "REFERENCE:" at 10322.5,3590.54 h60
  text "X" at 10979.74,3590.44 h60
  text "AS SHOWN" at 11157.73,3590.54 h60
  text "X" at 11880.74,3590.54 h60
  text "OTHER" at 12306.73,3448.29 h60
  text "PTH COPPER THICKNESS:" at 10322.18,3444.76 h60
  text "X" at 11461.41,3444.76 h60
  text "20-30 um" at 11589.41,3444.76 h60
  text "BOARD FINISH:" at 10247.73,3297.16 h60
  text "SILKSCREEN:" at 10402.95,3187.04 h60
  text "X" at 11360.74,3187.04 h60
  text "TOP" at 11477.73,3187.04 h60
  text "BOTTOM" at 11988.73,3187.04 h60
  text "SILKSCREEN COLOR:" at 10402.95,3031.85 h60
  text "X" at 11359.74,3031.85 h60
  text "WHITE" at 11477.73,3031.85 h60
  text "OTHER" at 11988.73,3031.85 h60
  text "X" at 11487.3,2892.33 h60
  text "GREEN" at 11608.73,2888.4 h60
  text "OTHER" at 12226.73,2888.4 h60
  text "SOLDER RESIST COLOR:" at 10402.95,2881.53 h60
  text "X" at 11490.74,2734.15 h60
  text "MATTE" at 11608.73,2734.15 h60
  text "SEMI-GLOSS" at 12226.27,2733.51 h60
  text "IMMERSION GOLD (ENIG)" at 11308.73,2561.38 h60
  text "ENEPIG" at 12646.27,2554.16 h60
  text "SURFACE FINISH:" at 10247.73,2553.16 h60
  text "X" at 11130.74,2553.16 h60
  text "IMM. TIN/SILVER OR EQUIV" at 10577.27,2415.84 h60
  text "OTHER" at 12008.73,2411.9 h60
  text "ARRAY/PANEL:" at 10247.73,2256.53 h60
  text "CUT AND TRIM PER M1 BOARD OUTLINE" at 11308.73,2248.3 h60
  text "N.C. ROUTE" at 11308.73,2112.34 h60
  text "V. SCORE" at 12174.73,2112.34 h60
  text "X" at 11991.92,2110.76 h60
  text "CERTIFICATION:" at 10247.73,1983.21 h60
  text "MATERIALS AND WORKMANSHIP FOR ALL PCBS" at 10972.73,1983.21 h60
  text "TO MEET OR EXCEED THE REQUIREMENTS OF:" at 10972.73,1889.15 h60
  text "X" at 10610.24,1760.52 h60
  text "ANSI IPC-A-600F CLASS ->" at 10738.23,1760.52 h60
  text "X" at 12386.24,1760.52 h60
  text "2" at 12496.23,1760.52 h60
  text "1" at 12181.23,1759.02 h60
  text "3" at 12850.23,1759.02 h60
  text "X" at 11422.24,1612.83 h60
  text "RoHS" at 11550.23,1612.83 h60
  text "OTHER" at 12194.64,1612.83 h60
  text "PER ORDER" at 12591.69,1612.83 h60
  text "ALL BOARDS MUST MEET OR EXCEED UL94-V0 REQUIREMENTS." at 10275.27,1459.01 h60
  text "PCB MUST BEAR THE UL94V-0 UL REGISTERED MATERIAL ID NUMBER" at 10275.27,1342.94 h60
  text "ADDITIONAL REQUIREMENTS:" at 10247.73,1173.52 h60
  text "MICROSECTION:" at 10322.5,1066.39 h60
  text "YES" at 11228.23,1066.39 h60
  text "REQUIRED" at 12089.73,922.06 h60
  text "BARE BOARD ELEC. TEST:" at 10322.5,919.2 h60
  text "NONE" at 11628.23,919.2 h60
  text "X" at 11971.74,919.2 h60
  text "PER ORDER" at 12681.73,919.2 h60
  text "XX MIL VIAS REQUIRE NON-CONDUCTIVE FILL AND PLANARIZE" at 10490.65,714.26 h59
  text "XX MIL VIAS REQUIRE CONDUCTIVE FILL AND PLANARIZE" at 10498.65,610.28 h60
  text "FAB NOTES:" at 4273.61,546.93 h60
  text "OUTER XX MIL VIAS REQUIRE 50 OHM SINGLE-ENDED IMPEDANCE" at 10497.66,446.89 h58
  text "1. THE SOLDER MASK IMAGES THAT ARE THE SAME SIZE AS THE COMPONENT PADS MAY BE ENLARGED AS PER THE" at 4285.55,398.79 h60
  text "LAYER 2 & 3 (INNER LAYERS) XX MIL WIDE, XX MIL SPACE" at 10497.78,291.96 h60
  text "MANUFACTURING CAPABILITIES BUT NOT BEYOND 0.08MM PER SIDE OR 0.15MM OVERALL." at 4446.89,265.18 h60
  text "ALL OTHER SOLDER MASK IMAGES SHALL NOT BE MODIFIED." at 4446.89,131.58 h60
  text ".Layer_Name" at -522.23,-1539.06 h60
M11 Gerber Information:
  lines w10: -1391.23,-1610.73 5208.77,-1610.73 ; -1391.23,-1407.4 5210.77,-1407.4 ; -1391.23,-1204.06 -1391.23,-1814.06 2613.77,-1814.06 5210.77,-1814.06 5210.77,-1204.06 -1390.73,-1204.06 -1390.73,-1814.06 184.77,-1814.06 ; 1073.77,-1814.06 1073.77,-1204.06 ; 2340.77,-1407.4 2340.77,-1204.06 ; 3180.77,-1407.4 3180.77,-1204.06 ; 3802.77,-1820.56 3802.77,-1617.73
  text "ALL ARTWORK VIEWED FROM TOP SIDE" at -1327.73,-1336.23 h60
  text "BOARD #:" at 1148.77,-1336.23 h60
  text ".PRJ_Number" at 1694.27,-1336.23 h60
  text "REV:" at 2538.77,-1336.23 h60
  text ".PCB_Rev" at 2830.27,-1336.23 h60
  text "SVN REV:" at 3376.77,-1336.23 h60
  text ".VersionControl_RevNumber" at 3882.77,-1336.23 h60
  text "LAYER NAME =" at -1327.73,-1539.06 h60
  text "TID #:" at 1148.77,-1539.56 h60
  text ".TID" at 1694.27,-1539.56 h60
  text "PLOT NAME =" at -1327.73,-1744.9 h60
  text ".plot_File_Name" at -522.23,-1744.9 h60
  text "GENERATED    :" at 1150.77,-1744.9 h60
  text ".Print_Date" at 2020.27,-1744.9 h60
  text ".Print_Time" at 2749.27,-1744.9 h60
  text "TEXAS INSTRUMENTS" at 4013.77,-1744.9 h60
M12 Stackup:
  drawing of 292 lines, arcs and shapes, not listed
  text "STACKUP TABLE:" at 4158.14,4148.01 h80
  text "Layer" at 4224.56,3976.37 h60
  text "Name" at 4634.47,3976.37 h60
  text "Material" at 5494.24,3976.37 h60
  text "Thickness" at 6354.01,3976.37 h60
  text "Constant" at 7003.84,3976.37 h60
  text "Board Layer Stack" at 7573.7,3976.37 h60
  text "Board Layer Stack" at 8693.39,3976.37 h60
  text "1" at 4224.56,3856.37 h60
  text "Top Overlay" at 4634.47,3856.37 h60
  text "2" at 4224.56,3736.37 h60
  text "Top Solder" at 4634.47,3736.37 h60
  text "Solder Resist" at 5494.24,3736.37 h60
  text "0.40mil" at 6354.01,3736.37 h60
  text "3.5" at 7003.84,3736.37 h60
  text "3" at 4224.56,3616.37 h60
  text "Top Layer" at 4634.47,3616.37 h60
  text "Copper" at 5494.24,3616.37 h60
  text "2.10mil" at 6354.01,3616.37 h60
  text "4" at 4224.56,3496.37 h60
  text "Dielectric1" at 4634.47,3496.37 h60
  text "FR-4 High Tg" at 5494.24,3496.37 h60
  text "57.00mil" at 6354.01,3496.37 h60
  text "4.8" at 7003.84,3496.37 h60
  text "5" at 4224.56,3376.37 h60
  text "Bottom Layer" at 4634.47,3376.37 h60
  text "Copper" at 5494.24,3376.37 h60
  text "2.10mil" at 6354.01,3376.37 h60
  text "6" at 4224.56,3256.37 h60
  text "Bottom Solder" at 4634.47,3256.37 h60
  text "Solder Resist" at 5494.24,3256.37 h60
  text "0.40mil" at 6354.01,3256.37 h60
  text "3.5" at 7003.84,3256.37 h60
  text ".Layer_Name" at -522.23,-1539.06 h60
M13 Component Bodies Top:
  text ".Layer_Name" at -522.23,-1539.06 h60
M14 Component Bodies Bottom:
  text ".Layer_Name" at -522.23,-1539.06 h60
M15 Courtyards Top:
  text ".Layer_Name" at -522.23,-1539.06 h60
M16 Courtyards Bottom:
  text ".Layer_Name" at -522.23,-1539.06 h60
Drill Drawing:
  lines w15: 4164.4,1816.6 9373.01,1816.6 ; 4164.4,2566.6 9373.01,2566.6 ; 4715.28,1666.6 4715.28,2716.6 ; 5255.14,1666.6 5255.14,2716.6 ; 6404.8,1666.6 6404.8,2716.6 ; 6910.68,1666.6 6910.68,2716.6 ; 7644.48,1666.6 7644.48,2716.6 ; 8750.16,1666.6 8750.16,2716.6 ; 4164.4,1666.6 9373.01,1666.6 9373.01,2716.6 4164.4,2716.6 4164.4,1666.6
  text "DRILL TABLE:" at 4165.14,2810.36 h80
  text "Symbol" at 4254.4,2611.6 h72
  text "Count" at 4760.28,2611.6 h72
  text "Hole Size" at 5300.14,2611.6 h72
  text "Plated" at 6449.8,2611.6 h72
  text "Hole Type" at 6955.68,2611.6 h72
  text "Tolerance(Mils)" at 7689.48,2611.6 h72
  text "Tenting" at 8795.16,2611.6 h72
  text "51" at 4760.28,2461.6 h60
  text "12.00mil (0.305mm)" at 5300.14,2461.6 h60
  text "PTH" at 6449.8,2461.6 h60
  text "Round" at 6955.68,2461.6 h60
  text "+0/-12" at 7689.48,2461.6 h60
  text "Both" at 8795.16,2461.6 h60
  text "A" at 4225.31,2451.61 h66.67
  text "13" at 4760.28,2311.6 h60
  text "63.00mil (1.600mm)" at 5300.14,2311.6 h60
  text "PTH" at 6449.8,2311.6 h60
  text "Round" at 6955.68,2311.6 h60
  text "+/-3" at 7689.48,2311.6 h60
  text "B" at 4225.31,2301.61 h66.67
  text "7" at 4760.28,2161.6 h60
  text "214.57mil (5.450mm)" at 5300.14,2161.6 h60
  text "PTH" at 6449.8,2161.6 h60
  text "Round" at 6955.68,2161.6 h60
  text "+/-3" at 7689.48,2161.6 h60
  text "E" at 4225.31,2151.61 h66.67
  text "4" at 4760.28,2011.6 h60
  text "125.98mil (3.200mm)" at 5300.14,2011.6 h60
  text "PTH" at 6449.8,2011.6 h60
  text "Round" at 6955.68,2011.6 h60
  text "+/-3" at 7689.48,2011.6 h60
  text "D" at 4225.31,2001.61 h66.67
  text "2" at 4760.28,1861.6 h60
  text "64.96mil (1.650mm)" at 5300.14,1861.6 h60
  text "PTH" at 6449.8,1861.6 h60
  text "Round" at 6955.68,1861.6 h60
  text "+/-3" at 7689.48,1861.6 h60
  text "C" at 4225.31,1851.61 h66.67
  text "77 Total" at 4760.28,1711.6 h60
  text ".Layer_Name" at -522.23,-1539.06 h60
M17 Embedded Cavity:
  text ".Layer_Name" at -522.23,-1539.06 h60
M18 Embedded Assembly:
  text ".Layer_Name" at -522.23,-1539.06 h60
M19 Embedded Keepout:
  text ".Layer_Name" at -522.23,-1539.06 h60

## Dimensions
-28.4,-30.18 to -312.94,-250.25 on M2 Board Dimensions
-1099.23,-1080.56 to -99.23,-1080.56 on M2 Board Dimensions
0,0 to 2950,-175 on M2 Board Dimensions
0,0 to -175,1925 on M2 Board Dimensions
0,0 to -175,-175 on M2 Board Dimensions
0,0 to -175,-175 on M2 Board Dimensions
